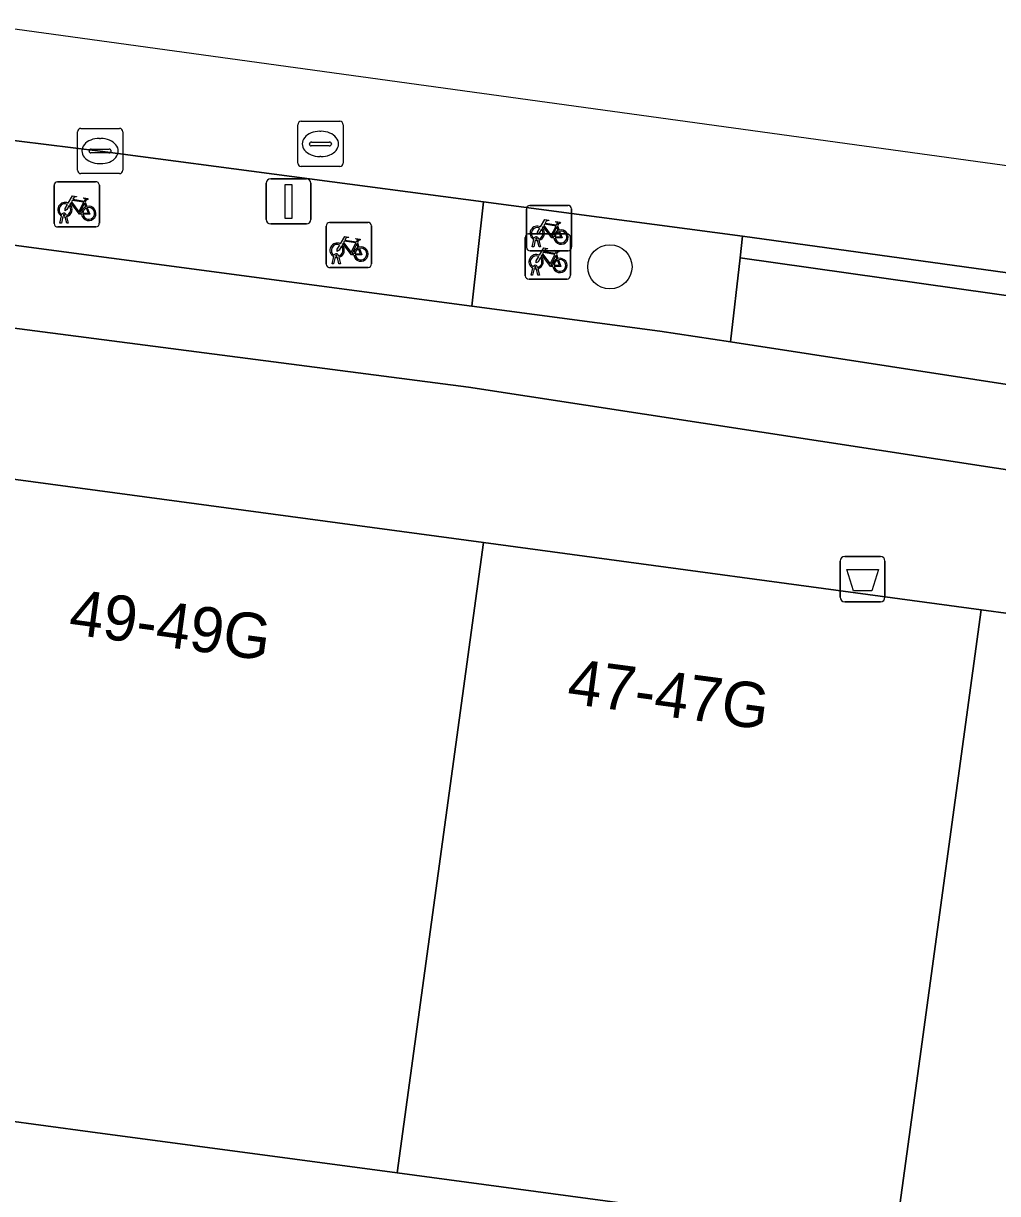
# Model space of a CAD drawing. Extents: x 160663 to 161506, y 382245 to 383291.
# Drawn here: x 160817.06 to 160838.6, y 383248.37 to 383274.23 of the extents above; entities that cross this region are included whole.
import ezdxf

# ---------------------------------------------------------------- set-up
doc = ezdxf.new("R2010")
doc.units = 0
for name, color, linetype in [('IMGEO_Afvalbak', 7, 'Continuous'), ('IMGEO_Berm_open', 7, 'Continuous'), ('IMGEO_Boom', 7, 'Continuous'), ('IMGEO_Erf', 7, 'Continuous'), ('IMGEO_Fietsenrek', 7, 'Continuous'), ('IMGEO_Fietspad_gesloten', 7, 'Continuous'), ('IMGEO_Groenvoorziening', 7, 'Continuous'), ('IMGEO_Kolk', 7, 'Continuous'), ('IMGEO_Lichtmast', 7, 'Continuous'), ('IMGEO_Pand', 7, 'Continuous'), ('IMGEO_Pand_nummerreeks', 7, 'Continuous'), ('IMGEO_Rijbaan_lokaal_gesloten', 7, 'Continuous'), ('IMGEO_Rioolput', 7, 'Continuous'), ('IMGEO_Voetpad_open', 7, 'Continuous')]:
    doc.layers.add(name, color=color, linetype=linetype)

msp = doc.modelspace()

# ---------------------------------------------------------------- linework, layer by layer
at = {"layer": 'IMGEO_Afvalbak'}
for p, q in [((160835.218, 383262.449), (160836.008, 383262.449)), ((160836.008, 383262.449), (160835.218, 383262.449)), ((160835.118, 383261.549), (160835.118, 383262.349)), ((160835.118, 383262.349), (160835.118, 383261.549)), ((160836.108, 383262.349), (160836.108, 383261.549)), ((160836.108, 383261.549), (160836.108, 383262.349)), ((160836.008, 383261.449), (160835.218, 383261.449)), ((160835.218, 383261.449), (160836.008, 383261.449))]:
    msp.add_line(p, q, dxfattribs=at)
msp.add_lwpolyline([(160835.261, 383262.163), (160835.965, 383262.163), (160835.816, 383261.693), (160835.41, 383261.693), (160835.261, 383262.163)], dxfattribs=at)
for centre, start, end in [((160835.218, 383262.349), 90, 180), ((160835.218, 383262.349), 90, 180), ((160836.008, 383262.349), 0, 90), ((160836.008, 383262.349), 360, 90), ((160835.218, 383261.549), 180, 270), ((160835.218, 383261.549), 180, 270), ((160836.008, 383261.549), 270, 0), ((160836.008, 383261.549), 270, 0)]:
    msp.add_arc(centre, 0.1, start, end, dxfattribs=at)
at = {"layer": 'IMGEO_Berm_open'}
for points in [[(160827.23, 383270.288), (160818.756, 383271.41), (160815.172, 383271.845), (160814.961, 383269.581), (160826.971, 383267.984)], [(160832.907, 383269.052), (160832.69, 383267.191), (160850.573, 383264.439), (160850.949, 383267.047), (160844.144, 383267.979), (160844.049, 383267.473)]]:
    msp.add_lwpolyline(points, close=True, dxfattribs=at)
at = {"layer": 'IMGEO_Boom'}
msp.add_circle((160830.026, 383268.851), 0.489, dxfattribs=at)
at = {"layer": 'IMGEO_Erf'}
msp.add_lwpolyline([(160836.327, 383247.348), (160825.326, 383248.825), (160818.534, 383249.737), (160816.578, 383250), (160814.324, 383250.303), (160805.265, 383251.519), (160803.323, 383251.78), (160792.22, 383253.271), (160791.772, 383250), (160789.293, 383231.893)], dxfattribs=at)
at = {"layer": 'IMGEO_Fietsenrek'}
for p, q in [((160817.814, 383270.731), (160818.655, 383270.731)), ((160818.655, 383270.731), (160817.814, 383270.731)), ((160817.739, 383269.806), (160817.739, 383270.647)), ((160817.739, 383270.647), (160817.739, 383269.806)), ((160818.739, 383270.656), (160818.739, 383269.815)), ((160818.739, 383269.815), (160818.739, 383270.656)), ((160818.426, 383270.28), (160818.462, 383270.185)), ((160828.255, 383270.207), (160829.096, 383270.207)), ((160829.096, 383270.207), (160828.255, 383270.207)), ((160817.866, 383269.815), (160817.905, 383269.975)), ((160817.935, 383269.963), (160817.9, 383269.815)), ((160817.977, 383269.987), (160817.976, 383269.991)), ((160818.018, 383269.815), (160817.984, 383269.957)), ((160818.008, 383269.998), (160818.009, 383269.991)), ((160818.016, 383269.961), (160818.051, 383269.815)), ((160828.18, 383269.282), (160828.18, 383270.123)), ((160828.18, 383270.123), (160828.18, 383269.282)), ((160829.18, 383270.132), (160829.18, 383269.291)), ((160829.18, 383269.291), (160829.18, 383270.132)), ((160818.664, 383269.731), (160817.823, 383269.731)), ((160817.823, 383269.731), (160818.664, 383269.731)), ((160817.9, 383269.815), (160817.866, 383269.815)), ((160818.051, 383269.815), (160818.018, 383269.815)), ((160823.756, 383268.907), (160823.756, 383269.748)), ((160823.756, 383269.748), (160823.756, 383268.907)), ((160823.831, 383269.832), (160824.672, 383269.832)), ((160824.672, 383269.832), (160823.831, 383269.832)), ((160824.756, 383269.757), (160824.756, 383268.916)), ((160824.756, 383268.916), (160824.756, 383269.757)), ((160828.867, 383269.756), (160828.903, 383269.661)), ((160828.155, 383268.654), (160828.155, 383269.495)), ((160828.155, 383269.495), (160828.155, 383268.654)), ((160828.23, 383269.579), (160829.071, 383269.579)), ((160829.071, 383269.579), (160828.23, 383269.579)), ((160828.307, 383269.291), (160828.346, 383269.451)), ((160828.376, 383269.439), (160828.341, 383269.291)), ((160828.418, 383269.463), (160828.417, 383269.467)), ((160828.459, 383269.291), (160828.425, 383269.433)), ((160828.449, 383269.474), (160828.45, 383269.467)), ((160828.457, 383269.437), (160828.492, 383269.291)), ((160829.155, 383269.504), (160829.155, 383268.663)), ((160829.155, 383268.663), (160829.155, 383269.504)), ((160824.443, 383269.381), (160824.479, 383269.286)), ((160829.105, 383269.207), (160828.264, 383269.207)), ((160828.264, 383269.207), (160829.105, 383269.207)), ((160828.341, 383269.291), (160828.307, 383269.291)), ((160828.492, 383269.291), (160828.459, 383269.291)), ((160823.883, 383268.916), (160823.922, 383269.076)), ((160823.917, 383268.916), (160823.883, 383268.916)), ((160823.952, 383269.064), (160823.917, 383268.916)), ((160823.994, 383269.088), (160823.993, 383269.092)), ((160824.035, 383268.916), (160824.001, 383269.058)), ((160824.025, 383269.099), (160824.026, 383269.092)), ((160824.033, 383269.062), (160824.068, 383268.916)), ((160824.068, 383268.916), (160824.035, 383268.916)), ((160828.842, 383269.128), (160828.878, 383269.033)), ((160824.681, 383268.832), (160823.84, 383268.832)), ((160823.84, 383268.832), (160824.681, 383268.832)), ((160828.282, 383268.663), (160828.321, 383268.823)), ((160828.316, 383268.663), (160828.282, 383268.663)), ((160828.351, 383268.811), (160828.316, 383268.663)), ((160828.393, 383268.835), (160828.392, 383268.839)), ((160828.434, 383268.663), (160828.4, 383268.805)), ((160828.424, 383268.846), (160828.425, 383268.839)), ((160828.432, 383268.809), (160828.467, 383268.663)), ((160828.467, 383268.663), (160828.434, 383268.663)), ((160829.08, 383268.579), (160828.239, 383268.579)), ((160828.239, 383268.579), (160829.08, 383268.579))]:
    msp.add_line(p, q, dxfattribs=at)
for points in [[(160818.073, 383270.205), (160818.021, 383270.115), (160817.981, 383270.09), (160817.982, 383270.137), (160818.037, 383270.231)], [(160818.052, 383270.257), (160818.147, 383270.421), (160818.233, 383270.407), (160818.235, 383270.398), (160818.179, 383270.387), (160818.152, 383270.342), (160818.408, 383270.301)], [(160818.348, 383270.013), (160818.298, 383270.013), (160818.107, 383270.264), (160818.088, 383270.232)], [(160818.395, 383270.276), (160818.138, 383270.317), (160818.121, 383270.288), (160818.288, 383270.068), (160818.395, 383270.276)], [(160818.443, 383270.178), (160818.413, 383270.255), (160818.304, 383270.037), (160818.347, 383270.037)], [(160818.408, 383270.301), (160818.433, 383270.35), (160818.427, 383270.354), (160818.404, 383270.358), (160818.392, 383270.365), (160818.391, 383270.368), (160818.393, 383270.373), (160818.488, 383270.358), (160818.49, 383270.348), (160818.48, 383270.335), (160818.468, 383270.329), (160818.454, 383270.335), (160818.426, 383270.28)], [(160818.377, 383270.037), (160818.497, 383270.036), (160818.453, 383270.15)], [(160818.473, 383270.157), (160818.528, 383270.012), (160818.378, 383270.012)], [(160828.514, 383269.681), (160828.462, 383269.591), (160828.422, 383269.566), (160828.423, 383269.613), (160828.478, 383269.707)], [(160828.493, 383269.733), (160828.588, 383269.897), (160828.674, 383269.883), (160828.676, 383269.874), (160828.62, 383269.863), (160828.593, 383269.818), (160828.849, 383269.777)], [(160828.789, 383269.489), (160828.739, 383269.489), (160828.548, 383269.74), (160828.529, 383269.708)], [(160828.836, 383269.752), (160828.579, 383269.793), (160828.562, 383269.764), (160828.729, 383269.544), (160828.836, 383269.752)], [(160828.884, 383269.654), (160828.854, 383269.731), (160828.745, 383269.513), (160828.788, 383269.513)], [(160828.849, 383269.777), (160828.874, 383269.826), (160828.868, 383269.83), (160828.845, 383269.834), (160828.833, 383269.841), (160828.832, 383269.844), (160828.834, 383269.849), (160828.929, 383269.834), (160828.931, 383269.824), (160828.921, 383269.811), (160828.909, 383269.805), (160828.895, 383269.811), (160828.867, 383269.756)], [(160824.069, 383269.358), (160824.164, 383269.522), (160824.25, 383269.508), (160824.252, 383269.499), (160824.196, 383269.488), (160824.169, 383269.443), (160824.425, 383269.402)], [(160824.412, 383269.377), (160824.155, 383269.418), (160824.138, 383269.389), (160824.305, 383269.169), (160824.412, 383269.377)], [(160824.425, 383269.402), (160824.45, 383269.451), (160824.444, 383269.455), (160824.421, 383269.459), (160824.409, 383269.466), (160824.408, 383269.469), (160824.41, 383269.474), (160824.505, 383269.459), (160824.507, 383269.449), (160824.497, 383269.436), (160824.485, 383269.43), (160824.471, 383269.436), (160824.443, 383269.381)], [(160828.818, 383269.513), (160828.938, 383269.512), (160828.894, 383269.626)], [(160828.914, 383269.633), (160828.969, 383269.488), (160828.819, 383269.488)], [(160824.09, 383269.306), (160824.038, 383269.216), (160823.998, 383269.191), (160823.999, 383269.238), (160824.054, 383269.332)], [(160824.365, 383269.114), (160824.315, 383269.114), (160824.124, 383269.365), (160824.105, 383269.333)], [(160824.46, 383269.279), (160824.43, 383269.356), (160824.321, 383269.138), (160824.364, 383269.138)], [(160824.394, 383269.138), (160824.514, 383269.137), (160824.47, 383269.251)], [(160824.49, 383269.258), (160824.545, 383269.113), (160824.395, 383269.113)], [(160828.468, 383269.105), (160828.563, 383269.269), (160828.649, 383269.255), (160828.651, 383269.246), (160828.595, 383269.235), (160828.568, 383269.19), (160828.824, 383269.149)], [(160828.811, 383269.124), (160828.554, 383269.165), (160828.537, 383269.136), (160828.704, 383268.916), (160828.811, 383269.124)], [(160828.824, 383269.149), (160828.849, 383269.198), (160828.843, 383269.202), (160828.82, 383269.206), (160828.808, 383269.213), (160828.807, 383269.216), (160828.809, 383269.221), (160828.904, 383269.206), (160828.906, 383269.196), (160828.896, 383269.183), (160828.884, 383269.177), (160828.87, 383269.183), (160828.842, 383269.128)], [(160828.489, 383269.053), (160828.437, 383268.963), (160828.397, 383268.938), (160828.398, 383268.985), (160828.453, 383269.079)], [(160828.764, 383268.861), (160828.714, 383268.861), (160828.523, 383269.112), (160828.504, 383269.08)], [(160828.859, 383269.026), (160828.829, 383269.103), (160828.72, 383268.885), (160828.763, 383268.885)], [(160828.793, 383268.885), (160828.913, 383268.884), (160828.869, 383268.998)], [(160828.889, 383269.005), (160828.944, 383268.86), (160828.794, 383268.86)]]:
    msp.add_lwpolyline(points, dxfattribs=at)
for centre, radius, start, end in [((160817.817, 383270.653), 0.0779, 92.4484, 184.2845), ((160817.817, 383270.653), 0.0779, 92.4484, 184.2845), ((160818.661, 383270.653), 0.0779, 2.4484, 94.2845), ((160818.661, 383270.653), 0.0779, 2.4484, 94.2845), ((160817.979, 383270.116), 0.159, 62.6766, 242.1369), ((160817.979, 383270.116), 0.129, 63.3192, 238.903), ((160817.979, 383270.116), 0.129, 283.6043, 43.4302), ((160817.979, 383270.116), 0.159, 283.5766, 46.6042), ((160818.506, 383270.032), 0.159, 113.3408, 178.3217), ((160818.506, 383270.032), 0.159, 187.0065, 105.7708), ((160828.258, 383270.129), 0.0779, 92.4484, 184.2845), ((160828.258, 383270.129), 0.0779, 92.4484, 184.2845), ((160829.102, 383270.129), 0.0779, 2.4484, 94.2845), ((160829.102, 383270.129), 0.0779, 2.4484, 94.2845), ((160817.959, 383269.987), 0.0499, 12.8025, 158.6934), ((160817.979, 383270.116), 0.159, 253.9967, 271.7867), ((160817.959, 383269.987), 0.0174, 12.8025, 163.4502), ((160817.979, 383270.116), 0.129, 253.415, 269.0204), ((160818.506, 383270.032), 0.129, 113.923, 177.9556), ((160818.506, 383270.032), 0.129, 188.6715, 104.5883), ((160817.817, 383269.809), 0.0779, 182.4484, 274.2845), ((160817.817, 383269.809), 0.0779, 182.4484, 274.2845), ((160818.661, 383269.809), 0.0779, 272.4484, 4.2845), ((160818.661, 383269.809), 0.0779, 272.4484, 4.2845), ((160823.834, 383269.754), 0.0779, 92.4484, 184.2845), ((160823.834, 383269.754), 0.0779, 92.4484, 184.2845), ((160824.678, 383269.754), 0.0779, 2.4484, 94.2845), ((160824.678, 383269.754), 0.0779, 2.4484, 94.2845), ((160828.42, 383269.592), 0.159, 62.6766, 242.1369), ((160828.42, 383269.592), 0.129, 63.3192, 238.903), ((160828.42, 383269.592), 0.129, 283.6043, 43.4302), ((160828.42, 383269.592), 0.159, 283.5766, 46.6042), ((160828.947, 383269.508), 0.159, 187.0065, 105.7708), ((160828.233, 383269.501), 0.0779, 92.4484, 184.2845), ((160828.233, 383269.501), 0.0779, 92.4484, 184.2845), ((160828.4, 383269.463), 0.0499, 12.8025, 158.6934), ((160828.42, 383269.592), 0.159, 253.9967, 271.7867), ((160828.4, 383269.463), 0.0174, 12.8025, 163.4502), ((160828.42, 383269.592), 0.129, 253.415, 269.0204), ((160828.947, 383269.508), 0.159, 113.3408, 178.3217), ((160828.947, 383269.508), 0.129, 113.923, 177.9556), ((160828.947, 383269.508), 0.129, 188.6715, 104.5883), ((160829.077, 383269.501), 0.0779, 2.4484, 94.2845), ((160829.077, 383269.501), 0.0779, 2.4484, 94.2845), ((160823.996, 383269.217), 0.159, 62.6766, 242.1369), ((160823.996, 383269.217), 0.129, 63.3192, 238.903), ((160823.996, 383269.217), 0.129, 283.6043, 43.4302), ((160823.996, 383269.217), 0.159, 283.5766, 46.6042), ((160824.523, 383269.133), 0.159, 113.3408, 178.3217), ((160824.523, 383269.133), 0.159, 187.0065, 105.7708), ((160824.523, 383269.133), 0.129, 113.923, 177.9556), ((160824.523, 383269.133), 0.129, 188.6715, 104.5883), ((160828.258, 383269.285), 0.0779, 182.4484, 274.2845), ((160828.258, 383269.285), 0.0779, 182.4484, 274.2845), ((160829.102, 383269.285), 0.0779, 272.4484, 4.2845), ((160829.102, 383269.285), 0.0779, 272.4484, 4.2845), ((160823.834, 383268.91), 0.0779, 182.4484, 274.2845), ((160823.834, 383268.91), 0.0779, 182.4484, 274.2845), ((160823.976, 383269.088), 0.0499, 12.8025, 158.6934), ((160823.996, 383269.217), 0.159, 253.9967, 271.7867), ((160823.976, 383269.088), 0.0174, 12.8025, 163.4502), ((160823.996, 383269.217), 0.129, 253.415, 269.0204), ((160824.678, 383268.91), 0.0779, 272.4484, 4.2845), ((160824.678, 383268.91), 0.0779, 272.4484, 4.2845), ((160828.395, 383268.964), 0.159, 62.6766, 242.1369), ((160828.395, 383268.964), 0.129, 63.3192, 238.903), ((160828.375, 383268.835), 0.0499, 12.8025, 158.6934), ((160828.395, 383268.964), 0.129, 283.6043, 43.4302), ((160828.395, 383268.964), 0.159, 283.5766, 46.6042), ((160828.922, 383268.88), 0.159, 113.3408, 178.3217), ((160828.922, 383268.88), 0.159, 187.0065, 105.7708), ((160828.922, 383268.88), 0.129, 113.923, 177.9556), ((160828.922, 383268.88), 0.129, 188.6715, 104.5883), ((160828.233, 383268.657), 0.0779, 182.4484, 274.2845), ((160828.233, 383268.657), 0.0779, 182.4484, 274.2845), ((160828.395, 383268.964), 0.159, 253.9967, 271.7867), ((160828.375, 383268.835), 0.0174, 12.8025, 163.4502), ((160828.395, 383268.964), 0.129, 253.415, 269.0204), ((160829.077, 383268.657), 0.0779, 272.4484, 4.2845), ((160829.077, 383268.657), 0.0779, 272.4484, 4.2845)]:
    msp.add_arc(centre, radius, start, end, dxfattribs=at)
at = {"layer": 'IMGEO_Fietspad_gesloten'}
for points in [[(160749.571, 383275.838), (160772.375, 383273.271), (160826.897, 383266.189), (160865.807, 383260.226), (160871.952, 383259.299), (160876.01, 383258.649), (160907.21, 383254.866), (160915.937, 383253.784), (160972.356, 383246.078), (160977.609, 383245.36), (160998.315, 383242.532), (161054.596, 383234.67)], [(160850.573, 383264.439), (160832.69, 383267.191), (160831.127, 383267.431), (160826.971, 383267.984), (160814.961, 383269.581), (160809.317, 383270.332), (160797.983, 383271.839), (160793.458, 383272.441), (160790.578, 383272.824)]]:
    msp.add_lwpolyline(points, dxfattribs=at)
at = {"layer": 'IMGEO_Groenvoorziening'}
msp.add_lwpolyline([(160832.907, 383269.052), (160832.959, 383269.529), (160827.23, 383270.288), (160826.971, 383267.984), (160831.127, 383267.431), (160832.69, 383267.191)], close=True, dxfattribs=at)
at = {"layer": 'IMGEO_Kolk'}
for p, q in [((160818.255, 383270.984), (160818.255, 383271.836)), ((160818.33, 383271.91), (160819.182, 383271.91)), ((160819.256, 383271.836), (160819.256, 383270.984)), ((160818.743, 383271.69), (160818.768, 383271.69)), ((160818.514, 383271.404), (160818.514, 383271.416)), ((160818.952, 383271.367), (160818.554, 383271.367)), ((160818.557, 383271.453), (160818.955, 383271.453)), ((160818.998, 383271.416), (160818.998, 383271.404)), ((160818.766, 383271.13), (160818.741, 383271.13)), ((160819.182, 383270.91), (160818.33, 383270.91))]:
    msp.add_line(p, q, dxfattribs=at)
for points in [[(160818.255, 383270.984), (160818.255, 383271.836)], [(160818.33, 383271.91), (160819.182, 383271.91)], [(160819.256, 383271.836), (160819.256, 383270.984)], [(160819.182, 383270.91), (160818.33, 383270.91)]]:
    msp.add_lwpolyline(points, dxfattribs=at)
for centre, radius, start, end in [((160818.332, 383271.834), 0.0765, 91.552, 178.448), ((160818.332, 383271.834), 0.0765, 91.552, 178.448), ((160819.18, 383271.834), 0.0765, 1.552, 88.448), ((160819.18, 383271.834), 0.0765, 1.552, 88.448), ((160818.554, 383271.413), 0.0403, 85.8775, 175.7526), ((160818.551, 383271.403), 0.0366, 178.938, 274.7102), ((160818.955, 383271.41), 0.043, 264.8664, 352.4533), ((160818.959, 383271.415), 0.0386, 1.7309, 96.639), ((160818.332, 383270.986), 0.0765, 181.552, 268.448), ((160818.332, 383270.986), 0.0765, 181.552, 268.448), ((160819.18, 383270.986), 0.0765, 271.552, 358.448), ((160819.18, 383270.986), 0.0765, 271.552, 358.448)]:
    msp.add_arc(centre, radius, start, end, dxfattribs=at)
for centre, major_axis, ratio, start_param, end_param in [((160818.742, 383271.41), (-0.387, 0.002), 0.722429, 4.712389, 7.853982), ((160818.767, 383271.41), (-0.39, 0.002), 0.717154, 1.570796, 4.712389)]:
    msp.add_ellipse(centre, major_axis=major_axis, ratio=ratio, start_param=start_param, end_param=end_param, dxfattribs=at)
at = {"layer": 'IMGEO_Lichtmast'}
for p, q in [((160822.428, 383269.897), (160822.428, 383270.697)), ((160822.428, 383270.697), (160822.428, 383269.897)), ((160822.528, 383270.797), (160823.318, 383270.797)), ((160823.318, 383270.797), (160822.528, 383270.797)), ((160823.418, 383270.697), (160823.418, 383269.897)), ((160823.418, 383269.897), (160823.418, 383270.697)), ((160823.318, 383269.797), (160822.528, 383269.797)), ((160822.528, 383269.797), (160823.318, 383269.797))]:
    msp.add_line(p, q, dxfattribs=at)
msp.add_lwpolyline([(160822.848, 383270.672), (160822.998, 383270.672), (160822.998, 383269.922), (160822.848, 383269.922), (160822.848, 383270.672)], dxfattribs=at)
for centre, start, end in [((160822.528, 383270.697), 90, 180), ((160822.528, 383270.697), 90, 180), ((160823.318, 383270.697), 0, 90), ((160823.318, 383270.697), 360, 90), ((160822.528, 383269.897), 180, 270), ((160822.528, 383269.897), 180, 270), ((160823.318, 383269.897), 270, 0), ((160823.318, 383269.897), 270, 0)]:
    msp.add_arc(centre, 0.1, start, end, dxfattribs=at)
at = {"layer": 'IMGEO_Pand'}
for points in [[(160814.324, 383250.303), (160816.578, 383250), (160818.534, 383249.737), (160825.326, 383248.825), (160827.231, 383262.757), (160816.231, 383264.24)], [(160836.383, 383247.748), (160836.696, 383250), (160838.231, 383261.273), (160827.231, 383262.757), (160825.326, 383248.825), (160836.327, 383247.348)], [(160844.135, 383260.477), (160838.231, 383261.273), (160836.696, 383250), (160836.383, 383247.748), (160836.327, 383247.348), (160836.012, 383245.041), (160836.173, 383244.792), (160837.196, 383243.209), (160840.056, 383245.035), (160841.04, 383252.186), (160842.958, 383251.922)]]:
    msp.add_lwpolyline(points, close=True, dxfattribs=at)
at = {"layer": 'IMGEO_Rijbaan_lokaal_gesloten'}
for points in [[(160896.852, 383263.09), (160789.689, 383277.854), (160760.039, 383281.939), (160749.307, 383283.418), (160711.318, 383288.264), (160711.312, 383287.33), (160715.419, 383286.99), (160715.607, 383286.974), (160720.29, 383286.426), (160726.296, 383285.597)], [(160766.303, 383277.669), (160770.217, 383277.218), (160776.779, 383276.461), (160784.806, 383275.536), (160787.715, 383275.191), (160787.829, 383275.177), (160790.757, 383274.806), (160793.692, 383274.45), (160798.216, 383273.901), (160809.55, 383272.527), (160815.172, 383271.845), (160818.756, 383271.41), (160827.23, 383270.288), (160832.959, 383269.529), (160844.144, 383267.979), (160850.949, 383267.047), (160856.311, 383266.312), (160862.548, 383265.458), (160878.331, 383263.145), (160896.51, 383260.689), (160896.612, 383261.407), (160896.852, 383263.09)]]:
    msp.add_lwpolyline(points, dxfattribs=at)
at = {"layer": 'IMGEO_Rioolput'}
for p, q in [((160823.126, 383271.14), (160823.126, 383271.992)), ((160823.201, 383272.066), (160824.053, 383272.066)), ((160824.127, 383271.992), (160824.127, 383271.14)), ((160823.614, 383271.846), (160823.639, 383271.846)), ((160823.385, 383271.56), (160823.385, 383271.572)), ((160823.823, 383271.523), (160823.425, 383271.523)), ((160823.428, 383271.609), (160823.826, 383271.609)), ((160823.869, 383271.572), (160823.869, 383271.56)), ((160823.637, 383271.286), (160823.612, 383271.286)), ((160824.053, 383271.066), (160823.201, 383271.066))]:
    msp.add_line(p, q, dxfattribs=at)
for points in [[(160823.126, 383271.14), (160823.126, 383271.992)], [(160823.201, 383272.066), (160824.053, 383272.066)], [(160824.127, 383271.992), (160824.127, 383271.14)], [(160824.053, 383271.066), (160823.201, 383271.066)]]:
    msp.add_lwpolyline(points, dxfattribs=at)
for centre, radius, start, end in [((160823.203, 383271.99), 0.0765, 91.552, 178.448), ((160823.203, 383271.99), 0.0765, 91.552, 178.448), ((160824.051, 383271.99), 0.0765, 1.552, 88.448), ((160824.051, 383271.99), 0.0765, 1.552, 88.448), ((160823.425, 383271.569), 0.0403, 85.8775, 175.7526), ((160823.422, 383271.559), 0.0366, 178.938, 274.7102), ((160823.826, 383271.566), 0.043, 264.8664, 352.4533), ((160823.83, 383271.571), 0.0386, 1.7309, 96.639), ((160823.203, 383271.142), 0.0765, 181.552, 268.448), ((160823.203, 383271.142), 0.0765, 181.552, 268.448), ((160824.051, 383271.142), 0.0765, 271.552, 358.448), ((160824.051, 383271.142), 0.0765, 271.552, 358.448)]:
    msp.add_arc(centre, radius, start, end, dxfattribs=at)
for centre, major_axis, ratio, start_param, end_param in [((160823.613, 383271.566), (-0.387, 0.002), 0.722429, 4.712389, 7.853982), ((160823.638, 383271.566), (-0.39, 0.002), 0.717154, 1.570796, 4.712389)]:
    msp.add_ellipse(centre, major_axis=major_axis, ratio=ratio, start_param=start_param, end_param=end_param, dxfattribs=at)
at = {"layer": 'IMGEO_Voetpad_open'}
for points in [[(160718.097, 383268.406), (160734.679, 383272.794), (160736.27, 383273.143), (160740.76, 383273.645), (160745.129, 383273.831), (160758.097, 383272.082), (160767.039, 383270.875), (160775.87, 383269.684), (160784.949, 383268.46), (160793.991, 383267.24), (160805.23, 383265.724), (160816.231, 383264.24), (160827.231, 383262.757), (160838.231, 383261.273), (160844.135, 383260.477), (160851.794, 383259.444), (160860.248, 383258.284), (160861.217, 383258.166), (160867.042, 383256.762), (160867.218, 383258.027)], [(160865.807, 383260.226), (160826.897, 383266.189), (160772.375, 383273.271)]]:
    msp.add_lwpolyline(points, dxfattribs=at)
msp.add_lwpolyline([(160844.144, 383267.979), (160832.959, 383269.529), (160832.907, 383269.052), (160844.049, 383267.473)], close=True, dxfattribs=at)

# ---------------------------------------------------------------- texts
at = {"layer": 'IMGEO_Pand_nummerreeks'}
for s, rotation, p in [('49-49G', 352.3332, (160818.036, 383260.74)), ('47-47G', 352.4215, (160829.054, 383259.206))]:
    msp.add_text(s, height=1, rotation=rotation, dxfattribs=at).set_placement(p)

doc.saveas('drawing.dxf')
